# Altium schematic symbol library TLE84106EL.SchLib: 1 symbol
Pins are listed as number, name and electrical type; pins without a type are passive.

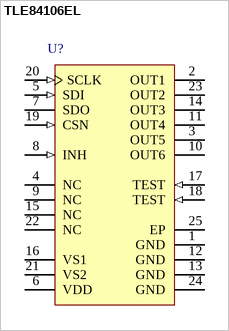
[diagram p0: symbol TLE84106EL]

## TLE84106EL
designator U?
Hex-Half-Bridge Driver IC, -40 to 150 degC, PG-SSOP-24-4, Reel, Green; Manufacturer: Infineon; PartNumber: TLE84106EL; Green: TRUE; Group: Multi Half Bridges; IPeak: 6 x 0.8; Iq: 6 x 0.5; Iq (typ): 2 uA; Operating Range: 7 to 18 V; Protect: SC, OT, UV, OV, OL
footprint INF-PG-SSOP-24-4_N (SOP, 24-Leads, Body 8.65x3.9mm, Pitch 0.65mm, Thermal Pad 6.65x2.9mm, IPC Medium Density)
footprint INF-PG-SSOP-24-4_L (SOP, 24-Leads, Body 8.65x3.9mm, Pitch 0.65mm, Thermal Pad 6.65x2.9mm, IPC High Density)
footprint INF-PG-SSOP-24-4_M (SOP, 24-Leads, Body 8.65x3.9mm, Pitch 0.65mm, Thermal Pad 6.65x2.9mm, IPC Low Density)
pins: 1 GND (power) "Ground", 2 OUT1 (power) "Power Half-Bridge 1", 3 OUT5 (power) "Power Half-Bridge 5", 4 NC "Not Connected. This pin can either be left open or connected to ground", 5 SDI (in) "Serial-Data-Input", 6 VDD (power) "Logic Supply Voltage", 7 SDO (hiz) "Serial-Data-Output", 8 INH (in) "Inhibit input with internal pull-down; Place device in standby mode by pulling the INH line LOW", 9 NC "Not Connected. This pin can either be left open or connected to ground", 10 OUT6 (power) "Power Half-Bridge 6", 11 OUT4 (power) "Power Half-Bridge 4", 12 GND (power) "Ground", 13 GND (power) "Ground", 14 OUT3 (power) "Power Half-Bridge 3", 15 NC "Not Connected. This pin can either be left open or connected to ground", 16 VS1 (power) "Power Supply Voltage for Group 1 supplying current to OUT 3, OUT 4, OUT 6.", 17 TEST (in) "Test input with internal pull down. Used for production test only. This pin should be left open or connected to ground on board.", 18 TEST (in) "Test input with internal pull down. Used for production test only. This pin should be left open or connected to ground on board.", 19 CSN (in) "Chip-Select-Not-Input", 20 SCLK (in) "Serial Clock Input", 21 VS2 (power) "Power Supply Voltage for Group 2 supplying current to OUT 1, OUT 2, OUT 5.", 22 NC "Not Connected. This pin can either be left open or connected to ground", 23 OUT2 (power) "Power Half-Bridge 2", 24 GND (power) "Ground", 25 EP "Exposed Die Pad; For cooling purposes only; Do not use as electrical ground"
